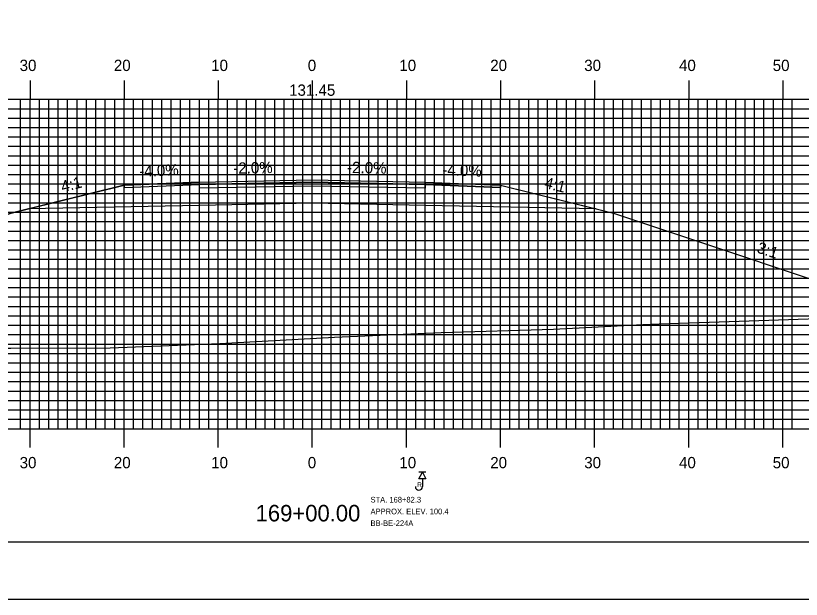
# Model space of a CAD drawing. Extents: x 1782254 to 1782597, y 442591 to 442811.
# Drawn here: x 1782387.9 to 1782471.4, y 442590.5 to 442652.5 of the extents above; entities that cross this region are included whole.
import ezdxf

# ---------------------------------------------------------------- set-up
doc = ezdxf.new("R2010")
doc.units = 0
for name, color, linetype in [('ANNOTATION', 7, 'Continuous'), ('BORDER', 7, 'Continuous'), ('D_Roadway_Centerline', 7, 'Continuous'), ('D_Roadway_Centerline_Text', 7, 'Continuous'), ('D_Roadway_Edge_Shoulder', 7, 'Continuous'), ('D_Roadway_Edge_TW', 7, 'Continuous'), ('D_Roadway_Pavement', 7, 'Continuous'), ('D_Roadway_SlopeLines', 7, 'Continuous'), ('D_Roadway_SubGrade', 7, 'Continuous'), ('H_V ANNOTATION', 7, 'Continuous'), ('MAJOR', 7, 'Continuous'), ('MINOR', 7, 'Continuous'), ('PLOT BOUNDARY', 7, 'Continuous'), ('ROCKS', 7, 'Continuous'), ('S_Roadway_Centerline', 7, 'Continuous')]:
    doc.layers.add(name, color=color, linetype=linetype)

msp = doc.modelspace()

# ---------------------------------------------------------------- linework, layer by layer
at = {"layer": 'BORDER'}
msp.add_lwpolyline([(1782269.834, 442596.665), (1782589.834, 442596.665), (1782589.834, 442806.665), (1782269.834, 442806.665)], close=True, dxfattribs=at)
at = {"layer": 'D_Roadway_Centerline'}
msp.add_lwpolyline([(1782337.713, 442614.979), (1782387.434, 442631.553), (1782389.26, 442632.009), (1782399.434, 442634.553), (1782407.434, 442634.873), (1782419.434, 442635.113), (1782431.434, 442634.873), (1782439.434, 442634.553), (1782449.608, 442632.009), (1782451.434, 442631.553), (1782482.544, 442621.183)], dxfattribs=at)
at = {"layer": 'D_Roadway_Edge_Shoulder'}
for points in [[(1782407.434, 442634.873), (1782399.434, 442634.553), (1782399.434, 442634.303), (1782407.434, 442634.623)], [(1782431.434, 442634.873), (1782439.434, 442634.553), (1782439.434, 442634.303), (1782431.434, 442634.623)]]:
    msp.add_lwpolyline(points, close=True, dxfattribs=at)
at = {"layer": 'D_Roadway_Edge_TW'}
msp.add_lwpolyline([(1782407.434, 442634.623), (1782407.434, 442634.873), (1782419.434, 442635.113), (1782431.434, 442634.873), (1782431.434, 442634.623), (1782419.434, 442634.863)], close=True, dxfattribs=at)
at = {"layer": 'D_Roadway_Pavement'}
msp.add_lwpolyline([(1782407.434, 442634.206), (1782407.434, 442634.623), (1782419.434, 442634.863), (1782431.434, 442634.623), (1782431.434, 442634.206), (1782419.434, 442634.446)], close=True, dxfattribs=at)
at = {"layer": 'D_Roadway_SlopeLines'}
for points in [[(1782399.434, 442634.553), (1782387.434, 442631.553), (1782337.713, 442614.979)], [(1782439.434, 442634.553), (1782451.434, 442631.553), (1782482.544, 442621.183)]]:
    msp.add_lwpolyline(points, dxfattribs=at)
at = {"layer": 'D_Roadway_SubGrade'}
msp.add_lwpolyline([(1782407.434, 442632.373), (1782389.26, 442632.009), (1782399.434, 442634.553), (1782399.434, 442634.303), (1782407.434, 442634.623), (1782419.434, 442634.863), (1782431.434, 442634.623), (1782439.434, 442634.303), (1782439.434, 442634.553), (1782449.608, 442632.009), (1782431.434, 442632.373), (1782419.434, 442632.613)], close=True, dxfattribs=at)
at = {"layer": 'MAJOR'}
for p, q in [((1782389.434, 442645.669), (1782389.434, 442643.665)), ((1782399.434, 442645.669), (1782399.434, 442643.665)), ((1782409.434, 442645.669), (1782409.434, 442643.665)), ((1782419.434, 442645.669), (1782419.434, 442643.665)), ((1782429.434, 442645.669), (1782429.434, 442643.665)), ((1782439.434, 442645.669), (1782439.434, 442643.665)), ((1782449.434, 442645.669), (1782449.434, 442643.665)), ((1782459.434, 442645.669), (1782459.434, 442643.665)), ((1782469.434, 442645.669), (1782469.434, 442643.665)), ((1782279.434, 442643.665), (1782559.434, 442643.665)), ((1782279.434, 442643.665), (1782559.434, 442643.665)), ((1782389.434, 442608.665), (1782389.434, 442643.665)), ((1782399.434, 442608.665), (1782399.434, 442643.665)), ((1782409.434, 442608.665), (1782409.434, 442643.665)), ((1782419.434, 442608.665), (1782419.434, 442643.665)), ((1782429.434, 442608.665), (1782429.434, 442643.665)), ((1782439.434, 442608.665), (1782439.434, 442643.665)), ((1782449.434, 442608.665), (1782449.434, 442643.665)), ((1782459.434, 442608.665), (1782459.434, 442643.665)), ((1782469.434, 442608.665), (1782469.434, 442643.665)), ((1782279.434, 442638.665), (1782559.434, 442638.665)), ((1782279.434, 442633.665), (1782559.434, 442633.665)), ((1782279.434, 442628.665), (1782559.434, 442628.665)), ((1782279.434, 442623.665), (1782559.434, 442623.665)), ((1782279.434, 442618.665), (1782559.434, 442618.665)), ((1782279.434, 442613.665), (1782559.434, 442613.665)), ((1782279.434, 442608.665), (1782559.434, 442608.665)), ((1782279.434, 442608.665), (1782559.434, 442608.665)), ((1782389.434, 442606.661), (1782389.434, 442608.665)), ((1782399.434, 442606.661), (1782399.434, 442608.665)), ((1782409.434, 442606.661), (1782409.434, 442608.665)), ((1782419.434, 442606.661), (1782419.434, 442608.665)), ((1782429.434, 442606.661), (1782429.434, 442608.665)), ((1782439.434, 442606.661), (1782439.434, 442608.665)), ((1782449.434, 442606.661), (1782449.434, 442608.665)), ((1782459.434, 442606.661), (1782459.434, 442608.665)), ((1782469.434, 442606.661), (1782469.434, 442608.665))]:
    msp.add_line(p, q, dxfattribs=at)
at = {"layer": 'MINOR'}
for p, q in [((1782388.434, 442608.665), (1782388.434, 442643.665)), ((1782390.434, 442608.665), (1782390.434, 442643.665)), ((1782391.434, 442608.665), (1782391.434, 442643.665)), ((1782392.434, 442608.665), (1782392.434, 442643.665)), ((1782393.434, 442608.665), (1782393.434, 442643.665)), ((1782394.434, 442608.665), (1782394.434, 442643.665)), ((1782395.434, 442608.665), (1782395.434, 442643.665)), ((1782396.434, 442608.665), (1782396.434, 442643.665)), ((1782397.434, 442608.665), (1782397.434, 442643.665)), ((1782398.434, 442608.665), (1782398.434, 442643.665)), ((1782400.434, 442608.665), (1782400.434, 442643.665)), ((1782401.434, 442608.665), (1782401.434, 442643.665)), ((1782402.434, 442608.665), (1782402.434, 442643.665)), ((1782403.434, 442608.665), (1782403.434, 442643.665)), ((1782404.434, 442608.665), (1782404.434, 442643.665)), ((1782405.434, 442608.665), (1782405.434, 442643.665)), ((1782406.434, 442608.665), (1782406.434, 442643.665)), ((1782407.434, 442608.665), (1782407.434, 442643.665)), ((1782408.434, 442608.665), (1782408.434, 442643.665)), ((1782410.434, 442608.665), (1782410.434, 442643.665)), ((1782411.434, 442608.665), (1782411.434, 442643.665)), ((1782412.434, 442608.665), (1782412.434, 442643.665)), ((1782413.434, 442608.665), (1782413.434, 442643.665)), ((1782414.434, 442608.665), (1782414.434, 442643.665)), ((1782415.434, 442608.665), (1782415.434, 442643.665)), ((1782416.434, 442608.665), (1782416.434, 442643.665)), ((1782417.434, 442608.665), (1782417.434, 442643.665)), ((1782418.434, 442608.665), (1782418.434, 442643.665)), ((1782420.434, 442608.665), (1782420.434, 442643.665)), ((1782421.434, 442608.665), (1782421.434, 442643.665)), ((1782422.434, 442608.665), (1782422.434, 442643.665)), ((1782423.434, 442608.665), (1782423.434, 442643.665)), ((1782424.434, 442608.665), (1782424.434, 442643.665)), ((1782425.434, 442608.665), (1782425.434, 442643.665)), ((1782426.434, 442608.665), (1782426.434, 442643.665)), ((1782427.434, 442608.665), (1782427.434, 442643.665)), ((1782428.434, 442608.665), (1782428.434, 442643.665)), ((1782430.434, 442608.665), (1782430.434, 442643.665)), ((1782431.434, 442608.665), (1782431.434, 442643.665)), ((1782432.434, 442608.665), (1782432.434, 442643.665)), ((1782433.434, 442608.665), (1782433.434, 442643.665)), ((1782434.434, 442608.665), (1782434.434, 442643.665)), ((1782435.434, 442608.665), (1782435.434, 442643.665)), ((1782436.434, 442608.665), (1782436.434, 442643.665)), ((1782437.434, 442608.665), (1782437.434, 442643.665)), ((1782438.434, 442608.665), (1782438.434, 442643.665)), ((1782440.434, 442608.665), (1782440.434, 442643.665)), ((1782441.434, 442608.665), (1782441.434, 442643.665)), ((1782442.434, 442608.665), (1782442.434, 442643.665)), ((1782443.434, 442608.665), (1782443.434, 442643.665)), ((1782444.434, 442608.665), (1782444.434, 442643.665)), ((1782445.434, 442608.665), (1782445.434, 442643.665)), ((1782446.434, 442608.665), (1782446.434, 442643.665)), ((1782447.434, 442608.665), (1782447.434, 442643.665)), ((1782448.434, 442608.665), (1782448.434, 442643.665)), ((1782450.434, 442608.665), (1782450.434, 442643.665)), ((1782451.434, 442608.665), (1782451.434, 442643.665)), ((1782452.434, 442608.665), (1782452.434, 442643.665)), ((1782453.434, 442608.665), (1782453.434, 442643.665)), ((1782454.434, 442608.665), (1782454.434, 442643.665)), ((1782455.434, 442608.665), (1782455.434, 442643.665)), ((1782456.434, 442608.665), (1782456.434, 442643.665)), ((1782457.434, 442608.665), (1782457.434, 442643.665)), ((1782458.434, 442608.665), (1782458.434, 442643.665)), ((1782460.434, 442608.665), (1782460.434, 442643.665)), ((1782461.434, 442608.665), (1782461.434, 442643.665)), ((1782462.434, 442608.665), (1782462.434, 442643.665)), ((1782463.434, 442608.665), (1782463.434, 442643.665)), ((1782464.434, 442608.665), (1782464.434, 442643.665)), ((1782465.434, 442608.665), (1782465.434, 442643.665)), ((1782466.434, 442608.665), (1782466.434, 442643.665)), ((1782467.434, 442608.665), (1782467.434, 442643.665)), ((1782468.434, 442608.665), (1782468.434, 442643.665)), ((1782470.434, 442608.665), (1782470.434, 442643.665)), ((1782279.434, 442642.665), (1782559.434, 442642.665)), ((1782279.434, 442641.665), (1782559.434, 442641.665)), ((1782279.434, 442640.665), (1782559.434, 442640.665)), ((1782279.434, 442639.665), (1782559.434, 442639.665)), ((1782279.434, 442637.665), (1782559.434, 442637.665)), ((1782279.434, 442636.665), (1782559.434, 442636.665)), ((1782279.434, 442635.665), (1782559.434, 442635.665)), ((1782279.434, 442634.665), (1782559.434, 442634.665)), ((1782279.434, 442632.665), (1782559.434, 442632.665)), ((1782279.434, 442631.665), (1782559.434, 442631.665)), ((1782279.434, 442630.665), (1782559.434, 442630.665)), ((1782279.434, 442629.665), (1782559.434, 442629.665)), ((1782279.434, 442627.665), (1782559.434, 442627.665)), ((1782279.434, 442626.665), (1782559.434, 442626.665)), ((1782279.434, 442625.665), (1782559.434, 442625.665)), ((1782279.434, 442624.665), (1782559.434, 442624.665)), ((1782279.434, 442622.665), (1782559.434, 442622.665)), ((1782279.434, 442621.665), (1782559.434, 442621.665)), ((1782279.434, 442620.665), (1782559.434, 442620.665)), ((1782279.434, 442619.665), (1782559.434, 442619.665)), ((1782279.434, 442617.665), (1782559.434, 442617.665)), ((1782279.434, 442616.665), (1782559.434, 442616.665)), ((1782279.434, 442615.665), (1782559.434, 442615.665)), ((1782279.434, 442614.665), (1782559.434, 442614.665)), ((1782279.434, 442612.665), (1782559.434, 442612.665)), ((1782279.434, 442611.665), (1782559.434, 442611.665)), ((1782279.434, 442610.665), (1782559.434, 442610.665)), ((1782279.434, 442609.665), (1782559.434, 442609.665))]:
    msp.add_line(p, q, dxfattribs=at)
at = {"layer": 'PLOT BOUNDARY'}
msp.add_lwpolyline([(1782253.647, 442590.547), (1782593.647, 442590.547), (1782593.647, 442810.547), (1782253.647, 442810.547)], close=True, dxfattribs=at)
at = {"layer": 'ROCKS'}
for p, q in [((1782431.503, 442604.065), (1782430.765, 442604.065)), ((1782431.134, 442603.327), (1782431.134, 442602.512))]:
    msp.add_line(p, q, dxfattribs=at)
msp.add_lwpolyline([(1782431.134, 442604.065), (1782431.503, 442603.327), (1782430.765, 442603.327)], close=True, dxfattribs=at)
msp.add_arc((1782430.761, 442602.512), 0.373, 180, 0, dxfattribs=at)
at = {"layer": 'S_Roadway_Centerline'}
msp.add_lwpolyline([(1782327.838, 442614.469), (1782337.054, 442614.949), (1782340.34, 442615.102), (1782342.994, 442615.091), (1782361.044, 442615.891), (1782363.292, 442616.044), (1782384.413, 442617.169), (1782385.365, 442617.223), (1782387.403, 442617.241), (1782397.961, 442617.266), (1782409.591, 442617.72), (1782409.9, 442617.726), (1782410.258, 442617.755), (1782421.793, 442618.388), (1782433.116, 442618.875), (1782445.07, 442619.258), (1782454.575, 442619.723), (1782456.282, 442619.793), (1782465.875, 442620.128), (1782477.353, 442620.52)], dxfattribs=at)

# ---------------------------------------------------------------- texts
at = {"layer": 'ANNOTATION'}
for s, rotation, p in [('-2.0%', 1.14576, (1782411.04, 442635.745)), ('-2.0%', 358.85424, (1782423.12, 442635.839)), ('-4.0%', 2.29061, (1782401.066, 442635.42)), ('-4.0%', 357.70939, (1782433.226, 442635.603)), ('4:1', 14.03624, (1782392.883, 442633.776)), ('4:1', 345.96376, (1782444.027, 442634.266)), ('3:1', 341.56522, (1782466.593, 442627.408))]:
    msp.add_text(s, height=1.2, rotation=rotation, dxfattribs=at).set_placement(p)
at = {"layer": 'D_Roadway_Centerline'}
for s, p in [('C', (1782419.429, 442635.113)), ('L', (1782419.434, 442635.105))]:
    msp.add_text(s, height=0.0146, dxfattribs=at).set_placement(p)
at = {"layer": 'D_Roadway_Centerline_Text'}
msp.add_text('131.45', height=1.2, dxfattribs=at).set_placement((1782416.968, 442644.034))
at = {"layer": 'H_V ANNOTATION'}
for s, height, p in [('30', 1.2, (1782388.331, 442646.665)), ('20', 1.2, (1782398.342, 442646.665)), ('10', 1.2, (1782408.685, 442646.665)), ('0', 1.2, (1782418.952, 442646.665)), ('10', 1.2, (1782428.685, 442646.665)), ('20', 1.2, (1782438.342, 442646.665)), ('30', 1.2, (1782448.331, 442646.665)), ('40', 1.2, (1782458.406, 442646.665)), ('50', 1.2, (1782468.363, 442646.665)), ('30', 1.2, (1782388.331, 442604.465)), ('20', 1.2, (1782398.342, 442604.465)), ('10', 1.2, (1782408.685, 442604.465)), ('0', 1.2, (1782418.952, 442604.465)), ('10', 1.2, (1782428.685, 442604.465)), ('20', 1.2, (1782438.342, 442604.465)), ('30', 1.2, (1782448.331, 442604.465)), ('40', 1.2, (1782458.406, 442604.465)), ('50', 1.2, (1782468.363, 442604.465)), ('169+00.00', 1.75, (1782413.41, 442598.821))]:
    msp.add_text(s, height=height, dxfattribs=at).set_placement(p)
at = {"layer": 'ROCKS'}
msp.add_text('R', height=0.492, dxfattribs=at).set_placement((1782430.589, 442602.47))
for s, p in [('STA. 168+82.3', (1782425.621, 442600.828)), ('APPROX. ELEV. 100.4', (1782425.621, 442599.578)), ('BB-BE-224A', (1782425.621, 442598.328))]:
    msp.add_text(s, height=0.6, rotation=360, dxfattribs=at).set_placement(p)

doc.saveas('drawing.dxf')
